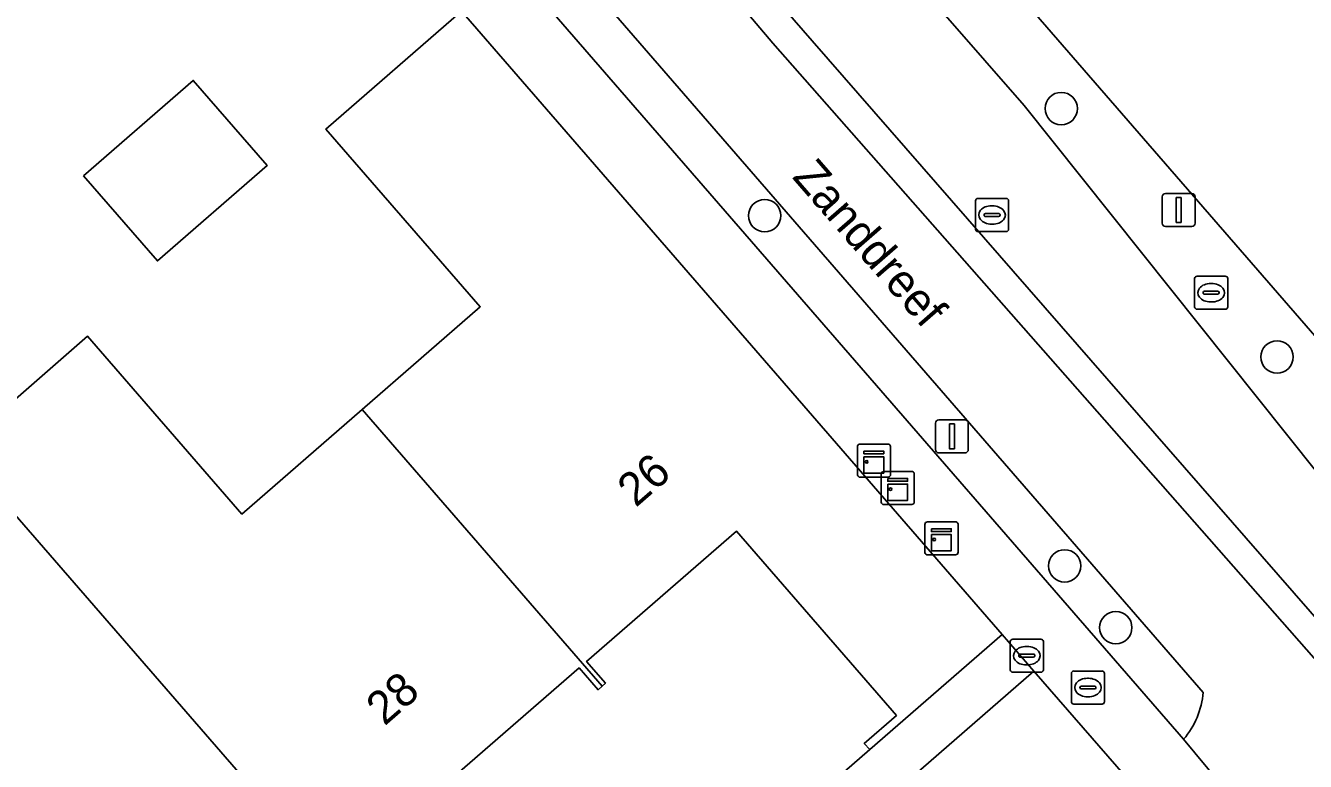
# Model space of a CAD drawing. Extents: x 155887 to 156869, y 383880 to 384678.
# Drawn here: x 156257.89 to 156296.57, y 384282.42 to 384304.63 of the extents above; entities that cross this region are included whole.
import ezdxf

# ---------------------------------------------------------------- set-up
doc = ezdxf.new("R2010")
doc.units = 0
for name, color, linetype in [('IMGEO_Berm_groen', 7, 'Continuous'), ('IMGEO_Boom', 7, 'Continuous'), ('IMGEO_Brandkraan', 7, 'Continuous'), ('IMGEO_Erf', 7, 'Continuous'), ('IMGEO_Fietspad_gesloten', 7, 'Continuous'), ('IMGEO_Greppel_droge_sloot', 7, 'Continuous'), ('IMGEO_Kast', 7, 'Continuous'), ('IMGEO_Kolk', 7, 'Continuous'), ('IMGEO_Lichtmast', 7, 'Continuous'), ('IMGEO_Openbare_ruimte_label', 7, 'Continuous'), ('IMGEO_OVBaan_gesloten', 7, 'Continuous'), ('IMGEO_Pand', 7, 'Continuous'), ('IMGEO_Pand_nummerreeks', 7, 'Continuous'), ('IMGEO_Parkeervlak_open', 7, 'Continuous'), ('IMGEO_Rioolput', 7, 'Continuous'), ('IMGEO_Voetpad_open', 7, 'Continuous')]:
    doc.layers.add(name, color=color, linetype=linetype)

msp = doc.modelspace()

# ---------------------------------------------------------------- linework, layer by layer
at = {"layer": 'IMGEO_Berm_groen'}
for points in [[(156336.14, 384250), (156299.846, 384291.826), (156254.404, 384344.112), (156249.976, 384340.147), (156249.797, 384339.996), (156255.055, 384333.785), (156258.691, 384329.477), (156261.912, 384325.993), (156263.306, 384324.351), (156280.478, 384304.105), (156290.275, 384292.985), (156298.297, 384283.879), (156305.293, 384275.816), (156311.875, 384268.489), (156315.179, 384264.541), (156318.171, 384261.203), (156320.09, 384258.879)], [(156248.065, 384336.788), (156247.015, 384335.884), (156292.888, 384283.087)], [(156293.476, 384284.503), (156248.065, 384336.788)]]:
    msp.add_lwpolyline(points, dxfattribs=at)
msp.add_lwpolyline([(156368.15, 384206.984), (156366.826, 384207.656), (156347.42, 384229.84), (156346.712, 384229.424), (156328.888, 384250), (156300.438, 384282.682), (156281.665, 384304.177), (156250.888, 384339.475), (156253.839, 384342.093), (156284.501, 384306.304), (156288.071, 384302.223), (156298.666, 384288.958), (156332.451, 384250), (156348.753, 384231.201), (156348.499, 384230.919), (156368.479, 384208.305), (156368.644, 384207.432)], close=True, dxfattribs=at)
msp.add_arc((156290.997, 384284.703), 2.487, 319.4991, 355.3992, dxfattribs=at)
at = {"layer": 'IMGEO_Boom'}
for centre in [(156289.189, 384302.13), (156280.228, 384298.897), (156295.711, 384294.631), (156289.292, 384288.323), (156290.837, 384286.459)]:
    msp.add_circle(centre, 0.489, dxfattribs=at)
at = {"layer": 'IMGEO_Brandkraan'}
for p, q in [((156287.723, 384286.111), (156288.575, 384286.111)), ((156287.648, 384285.185), (156287.648, 384286.037)), ((156288.136, 384285.891), (156288.161, 384285.891)), ((156288.649, 384286.037), (156288.649, 384285.185)), ((156287.907, 384285.605), (156287.907, 384285.617)), ((156288.345, 384285.568), (156287.947, 384285.568)), ((156287.95, 384285.654), (156288.348, 384285.654)), ((156288.391, 384285.617), (156288.391, 384285.605)), ((156288.575, 384285.111), (156287.723, 384285.111)), ((156288.159, 384285.331), (156288.134, 384285.331)), ((156289.495, 384284.223), (156289.495, 384285.075)), ((156289.57, 384285.149), (156290.422, 384285.149)), ((156290.496, 384285.075), (156290.496, 384284.223)), ((156289.754, 384284.643), (156289.754, 384284.655)), ((156290.192, 384284.606), (156289.794, 384284.606)), ((156289.797, 384284.692), (156290.195, 384284.692)), ((156289.983, 384284.929), (156290.008, 384284.929)), ((156290.238, 384284.655), (156290.238, 384284.643)), ((156290.006, 384284.369), (156289.981, 384284.369)), ((156290.422, 384284.149), (156289.57, 384284.149))]:
    msp.add_line(p, q, dxfattribs=at)
for points in [[(156287.723, 384286.111), (156288.575, 384286.111)], [(156287.648, 384285.185), (156287.648, 384286.037)], [(156288.649, 384286.037), (156288.649, 384285.185)], [(156288.575, 384285.111), (156287.723, 384285.111)], [(156289.495, 384284.223), (156289.495, 384285.075)], [(156289.57, 384285.149), (156290.422, 384285.149)], [(156290.496, 384285.075), (156290.496, 384284.223)], [(156290.422, 384284.149), (156289.57, 384284.149)]]:
    msp.add_lwpolyline(points, dxfattribs=at)
for centre, radius, start, end in [((156287.725, 384286.035), 0.0765, 91.552, 178.448), ((156287.725, 384286.035), 0.0765, 91.552, 178.448), ((156288.573, 384286.035), 0.0765, 1.552, 88.448), ((156288.573, 384286.035), 0.0765, 1.552, 88.448), ((156287.947, 384285.614), 0.0403, 85.8775, 175.7526), ((156287.944, 384285.604), 0.0366, 178.938, 274.7102), ((156288.348, 384285.611), 0.043, 264.8664, 352.4533), ((156288.352, 384285.616), 0.0386, 1.7309, 96.639), ((156287.725, 384285.187), 0.0765, 181.552, 268.448), ((156287.725, 384285.187), 0.0765, 181.552, 268.448), ((156288.573, 384285.187), 0.0765, 271.552, 358.448), ((156288.573, 384285.187), 0.0765, 271.552, 358.448), ((156289.572, 384285.073), 0.0765, 91.552, 178.448), ((156289.572, 384285.073), 0.0765, 91.552, 178.448), ((156290.42, 384285.073), 0.0765, 1.552, 88.448), ((156290.42, 384285.073), 0.0765, 1.552, 88.448), ((156289.794, 384284.652), 0.0403, 85.8775, 175.7526), ((156289.791, 384284.642), 0.0366, 178.938, 274.7102), ((156290.195, 384284.649), 0.043, 264.8664, 352.4533), ((156290.199, 384284.654), 0.0386, 1.7309, 96.639), ((156289.572, 384284.225), 0.0765, 181.552, 268.448), ((156289.572, 384284.225), 0.0765, 181.552, 268.448), ((156290.42, 384284.225), 0.0765, 271.552, 358.448), ((156290.42, 384284.225), 0.0765, 271.552, 358.448)]:
    msp.add_arc(centre, radius, start, end, dxfattribs=at)
for centre, major_axis, ratio, start_param, end_param in [((156288.135, 384285.611), (-0.387, 0.002), 0.722429, 4.712389, 7.853982), ((156288.16, 384285.611), (-0.39, 0.002), 0.717154, 1.570796, 4.712389), ((156289.982, 384284.649), (-0.387, 0.002), 0.722429, 4.712389, 7.853982), ((156290.007, 384284.649), (-0.39, 0.002), 0.717154, 1.570796, 4.712389)]:
    msp.add_ellipse(centre, major_axis=major_axis, ratio=ratio, start_param=start_param, end_param=end_param, dxfattribs=at)
at = {"layer": 'IMGEO_Erf'}
msp.add_lwpolyline([(156222.851, 384268.495), (156226.866, 384272.016), (156227.303, 384271.525), (156229.535, 384269.017), (156234.215, 384263.633), (156237.846, 384266.788), (156241.446, 384269.916), (156236.782, 384275.282), (156240.753, 384278.732), (156244.648, 384282.117), (156249.312, 384276.751), (156252.943, 384279.906), (156256.551, 384283.041), (156251.887, 384288.407), (156254.725, 384290.873), (156252.708, 384293.195), (156255.163, 384295.328), (156257.18, 384293.007), (156259.767, 384295.255), (156264.431, 384289.889), (156268.062, 384293.044), (156271.633, 384296.146), (156266.969, 384301.512), (156271.067, 384305.073)], dxfattribs=at)
for points in [[(156259.643, 384300.098), (156262.957, 384302.978), (156265.188, 384300.411), (156261.874, 384297.531)], [(156283.4, 384282.776), (156283.237, 384282.965), (156284.208, 384283.81), (156279.374, 384289.373), (156274.845, 384285.438), (156275.416, 384284.782), (156275.317, 384284.696), (156275.19, 384284.585), (156274.619, 384285.241), (156270.089, 384281.305), (156274.923, 384275.741), (156275.868, 384276.562), (156276.031, 384276.373)]]:
    msp.add_lwpolyline(points, close=True, dxfattribs=at)
at = {"layer": 'IMGEO_Fietspad_gesloten'}
for points in [[(156249.797, 384339.996), (156248.552, 384341.467), (156247.246, 384342.959), (156244.762, 384340.663), (156246.616, 384338.427), (156248.065, 384336.788), (156293.476, 384284.503)], [(156320.09, 384258.879), (156318.171, 384261.203), (156315.179, 384264.541), (156311.875, 384268.489), (156305.293, 384275.816), (156298.297, 384283.879), (156290.275, 384292.985), (156280.478, 384304.105), (156263.306, 384324.351), (156261.912, 384325.993), (156258.691, 384329.477), (156255.055, 384333.785), (156249.797, 384339.996)], [(156292.888, 384283.087), (156295.435, 384280.018)]]:
    msp.add_lwpolyline(points, dxfattribs=at)
msp.add_arc((156290.997, 384284.703), 2.487, 319.4991, 355.3992, dxfattribs=at)
at = {"layer": 'IMGEO_Greppel_droge_sloot'}
msp.add_lwpolyline([(156368.15, 384206.984), (156368.644, 384207.432), (156368.479, 384208.305), (156348.499, 384230.919), (156348.753, 384231.201), (156332.451, 384250), (156298.666, 384288.958), (156288.071, 384302.223), (156284.501, 384306.304), (156253.839, 384342.093), (156250.888, 384339.475), (156281.665, 384304.177), (156300.438, 384282.682), (156328.888, 384250), (156346.712, 384229.424), (156347.42, 384229.84), (156366.826, 384207.656)], close=True, dxfattribs=at)
at = {"layer": 'IMGEO_Kast'}
for p, q in [((156283.031, 384291.076), (156283.031, 384291.917)), ((156283.031, 384291.917), (156283.031, 384291.076)), ((156283.106, 384292.001), (156283.947, 384292.001)), ((156283.947, 384292.001), (156283.106, 384292.001)), ((156284.031, 384291.926), (156284.031, 384291.085)), ((156284.031, 384291.085), (156284.031, 384291.926)), ((156283.824, 384291.175), (156284.665, 384291.175)), ((156284.665, 384291.175), (156283.824, 384291.175)), ((156283.956, 384291.001), (156283.115, 384291.001)), ((156283.115, 384291.001), (156283.956, 384291.001)), ((156283.749, 384290.25), (156283.749, 384291.091)), ((156283.749, 384291.091), (156283.749, 384290.25)), ((156284.749, 384291.1), (156284.749, 384290.259)), ((156284.749, 384290.259), (156284.749, 384291.1)), ((156284.674, 384290.175), (156283.833, 384290.175)), ((156283.833, 384290.175), (156284.674, 384290.175)), ((156285.145, 384289.654), (156285.986, 384289.654)), ((156285.986, 384289.654), (156285.145, 384289.654)), ((156285.07, 384288.729), (156285.07, 384289.57)), ((156285.07, 384289.57), (156285.07, 384288.729)), ((156286.07, 384289.579), (156286.07, 384288.738)), ((156286.07, 384288.738), (156286.07, 384289.579)), ((156285.995, 384288.654), (156285.154, 384288.654)), ((156285.154, 384288.654), (156285.995, 384288.654))]:
    msp.add_line(p, q, dxfattribs=at)
for points in [[(156283.226, 384291.791), (156283.826, 384291.791), (156283.826, 384291.706), (156283.226, 384291.706), (156283.226, 384291.791)], [(156283.226, 384291.616), (156283.826, 384291.616), (156283.826, 384291.127), (156283.226, 384291.127), (156283.226, 384291.616)], [(156283.944, 384290.965), (156284.544, 384290.965), (156284.544, 384290.88), (156283.944, 384290.88), (156283.944, 384290.965)], [(156283.944, 384290.79), (156284.544, 384290.79), (156284.544, 384290.301), (156283.944, 384290.301), (156283.944, 384290.79)], [(156285.265, 384289.444), (156285.865, 384289.444), (156285.865, 384289.359), (156285.265, 384289.359), (156285.265, 384289.444)], [(156285.265, 384289.269), (156285.865, 384289.269), (156285.865, 384288.78), (156285.265, 384288.78), (156285.265, 384289.269)]]:
    msp.add_lwpolyline(points, dxfattribs=at)
for centre in [(156283.31, 384291.465), (156284.028, 384290.639), (156285.349, 384289.118)]:
    msp.add_circle(centre, 0.0377, dxfattribs=at)
for centre, start, end in [((156283.109, 384291.923), 92.4484, 184.2845), ((156283.109, 384291.923), 92.4484, 184.2845), ((156283.953, 384291.923), 2.4484, 94.2845), ((156283.953, 384291.923), 2.4484, 94.2845), ((156283.827, 384291.097), 92.4484, 184.2845), ((156283.827, 384291.097), 92.4484, 184.2845), ((156284.671, 384291.097), 2.4484, 94.2845), ((156284.671, 384291.097), 2.4484, 94.2845), ((156283.109, 384291.079), 182.4484, 274.2845), ((156283.109, 384291.079), 182.4484, 274.2845), ((156283.953, 384291.079), 272.4484, 4.2845), ((156283.953, 384291.079), 272.4484, 4.2845), ((156283.827, 384290.253), 182.4484, 274.2845), ((156283.827, 384290.253), 182.4484, 274.2845), ((156284.671, 384290.253), 272.4484, 4.2845), ((156284.671, 384290.253), 272.4484, 4.2845), ((156285.148, 384289.576), 92.4484, 184.2845), ((156285.148, 384289.576), 92.4484, 184.2845), ((156285.992, 384289.576), 2.4484, 94.2845), ((156285.992, 384289.576), 2.4484, 94.2845), ((156285.148, 384288.732), 182.4484, 274.2845), ((156285.148, 384288.732), 182.4484, 274.2845), ((156285.992, 384288.732), 272.4484, 4.2845), ((156285.992, 384288.732), 272.4484, 4.2845)]:
    msp.add_arc(centre, 0.0779, start, end, dxfattribs=at)
at = {"layer": 'IMGEO_Kolk'}
for p, q in [((156286.598, 384298.491), (156286.598, 384299.343)), ((156286.673, 384299.417), (156287.525, 384299.417)), ((156287.599, 384299.343), (156287.599, 384298.491)), ((156286.857, 384298.911), (156286.857, 384298.923)), ((156287.295, 384298.874), (156286.897, 384298.874)), ((156286.9, 384298.96), (156287.298, 384298.96)), ((156287.086, 384299.197), (156287.111, 384299.197)), ((156287.341, 384298.923), (156287.341, 384298.911)), ((156287.109, 384298.637), (156287.084, 384298.637)), ((156287.525, 384298.417), (156286.673, 384298.417))]:
    msp.add_line(p, q, dxfattribs=at)
for points in [[(156286.598, 384298.491), (156286.598, 384299.343)], [(156286.673, 384299.417), (156287.525, 384299.417)], [(156287.599, 384299.343), (156287.599, 384298.491)], [(156287.525, 384298.417), (156286.673, 384298.417)]]:
    msp.add_lwpolyline(points, dxfattribs=at)
for centre, radius, start, end in [((156286.675, 384299.341), 0.0765, 91.552, 178.448), ((156286.675, 384299.341), 0.0765, 91.552, 178.448), ((156287.523, 384299.341), 0.0765, 1.552, 88.448), ((156287.523, 384299.341), 0.0765, 1.552, 88.448), ((156286.897, 384298.92), 0.0403, 85.8775, 175.7526), ((156286.894, 384298.91), 0.0366, 178.938, 274.7102), ((156287.298, 384298.917), 0.043, 264.8664, 352.4533), ((156287.302, 384298.922), 0.0386, 1.7309, 96.639), ((156286.675, 384298.493), 0.0765, 181.552, 268.448), ((156286.675, 384298.493), 0.0765, 181.552, 268.448), ((156287.523, 384298.493), 0.0765, 271.552, 358.448), ((156287.523, 384298.493), 0.0765, 271.552, 358.448)]:
    msp.add_arc(centre, radius, start, end, dxfattribs=at)
for centre, major_axis, ratio, start_param, end_param in [((156287.085, 384298.917), (-0.387, 0.002), 0.722429, 4.712389, 7.853982), ((156287.11, 384298.917), (-0.39, 0.002), 0.717154, 1.570796, 4.712389)]:
    msp.add_ellipse(centre, major_axis=major_axis, ratio=ratio, start_param=start_param, end_param=end_param, dxfattribs=at)
at = {"layer": 'IMGEO_Lichtmast'}
for p, q in [((156292.242, 384298.667), (156292.242, 384299.467)), ((156292.242, 384299.467), (156292.242, 384298.667)), ((156292.342, 384299.567), (156293.132, 384299.567)), ((156293.132, 384299.567), (156292.342, 384299.567)), ((156293.232, 384299.467), (156293.232, 384298.667)), ((156293.232, 384298.667), (156293.232, 384299.467)), ((156293.132, 384298.567), (156292.342, 384298.567)), ((156292.342, 384298.567), (156293.132, 384298.567)), ((156285.49, 384292.733), (156286.28, 384292.733)), ((156286.28, 384292.733), (156285.49, 384292.733)), ((156285.39, 384291.833), (156285.39, 384292.633)), ((156285.39, 384292.633), (156285.39, 384291.833)), ((156286.38, 384292.633), (156286.38, 384291.833)), ((156286.38, 384291.833), (156286.38, 384292.633)), ((156286.28, 384291.733), (156285.49, 384291.733)), ((156285.49, 384291.733), (156286.28, 384291.733))]:
    msp.add_line(p, q, dxfattribs=at)
for points in [[(156292.662, 384299.442), (156292.812, 384299.442), (156292.812, 384298.692), (156292.662, 384298.692), (156292.662, 384299.442)], [(156285.81, 384292.608), (156285.96, 384292.608), (156285.96, 384291.858), (156285.81, 384291.858), (156285.81, 384292.608)]]:
    msp.add_lwpolyline(points, dxfattribs=at)
for centre, start, end in [((156292.342, 384299.467), 90, 180), ((156292.342, 384299.467), 90, 180), ((156293.132, 384299.467), 0, 90), ((156293.132, 384299.467), 360, 90), ((156292.342, 384298.667), 180, 270), ((156292.342, 384298.667), 180, 270), ((156293.132, 384298.667), 270, 0), ((156293.132, 384298.667), 270, 0), ((156285.49, 384292.633), 90, 180), ((156285.49, 384292.633), 90, 180), ((156286.28, 384292.633), 0, 90), ((156286.28, 384292.633), 360, 90), ((156285.49, 384291.833), 180, 270), ((156285.49, 384291.833), 180, 270), ((156286.28, 384291.833), 270, 0), ((156286.28, 384291.833), 270, 0)]:
    msp.add_arc(centre, 0.1, start, end, dxfattribs=at)
at = {"layer": 'IMGEO_OVBaan_gesloten'}
msp.add_lwpolyline([(156344.918, 384250), (156310.449, 384289.788), (156259.398, 384348.45), (156254.404, 384344.112), (156299.846, 384291.826), (156336.14, 384250)], dxfattribs=at)
at = {"layer": 'IMGEO_Pand'}
for points in [[(156275.317, 384284.696), (156275.416, 384284.782), (156274.845, 384285.438), (156279.374, 384289.373), (156284.208, 384283.81), (156283.237, 384282.965), (156283.4, 384282.776), (156287.4, 384286.252), (156271.067, 384305.073), (156266.969, 384301.512), (156271.633, 384296.146), (156268.062, 384293.044)], [(156259.643, 384300.098), (156261.874, 384297.531), (156265.188, 384300.411), (156262.957, 384302.978)], [(156268.062, 384293.044), (156264.431, 384289.889), (156259.767, 384295.255), (156257.18, 384293.007), (156255.842, 384291.844), (156272.197, 384273.042), (156276.031, 384276.373), (156275.868, 384276.562), (156274.923, 384275.741), (156270.089, 384281.305), (156274.619, 384285.241), (156275.19, 384284.585), (156275.317, 384284.696)], [(156255.842, 384291.844), (156254.725, 384290.873), (156251.887, 384288.407), (156256.551, 384283.041), (156252.943, 384279.906), (156260.214, 384271.572), (156260.319, 384271.664), (156259.748, 384272.32), (156264.277, 384276.255), (156269.111, 384270.691), (156268.169, 384269.873), (156268.332, 384269.684), (156272.197, 384273.042)]]:
    msp.add_lwpolyline(points, close=True, dxfattribs=at)
at = {"layer": 'IMGEO_Parkeervlak_open'}
msp.add_lwpolyline([(156291.002, 384281.43), (156291.342, 384281.726), (156288.362, 384285.147), (156247.93, 384250), (156242.787, 384245.529), (156245.758, 384242.109), (156254.838, 384250)], close=True, dxfattribs=at)
at = {"layer": 'IMGEO_Rioolput'}
for p, q in [((156293.219, 384296.144), (156293.219, 384296.996)), ((156293.294, 384297.07), (156294.146, 384297.07)), ((156294.22, 384296.996), (156294.22, 384296.144)), ((156293.478, 384296.564), (156293.478, 384296.576)), ((156293.521, 384296.613), (156293.919, 384296.613)), ((156293.707, 384296.85), (156293.732, 384296.85)), ((156293.962, 384296.576), (156293.962, 384296.564)), ((156293.916, 384296.527), (156293.518, 384296.527)), ((156293.73, 384296.29), (156293.705, 384296.29)), ((156294.146, 384296.07), (156293.294, 384296.07))]:
    msp.add_line(p, q, dxfattribs=at)
for points in [[(156293.219, 384296.144), (156293.219, 384296.996)], [(156293.294, 384297.07), (156294.146, 384297.07)], [(156294.22, 384296.996), (156294.22, 384296.144)], [(156294.146, 384296.07), (156293.294, 384296.07)]]:
    msp.add_lwpolyline(points, dxfattribs=at)
for centre, radius, start, end in [((156293.296, 384296.994), 0.0765, 91.552, 178.448), ((156293.296, 384296.994), 0.0765, 91.552, 178.448), ((156294.144, 384296.994), 0.0765, 1.552, 88.448), ((156294.144, 384296.994), 0.0765, 1.552, 88.448), ((156293.518, 384296.573), 0.0403, 85.8775, 175.7526), ((156293.515, 384296.563), 0.0366, 178.938, 274.7102), ((156293.919, 384296.57), 0.043, 264.8664, 352.4533), ((156293.923, 384296.575), 0.0386, 1.7309, 96.639), ((156293.296, 384296.146), 0.0765, 181.552, 268.448), ((156293.296, 384296.146), 0.0765, 181.552, 268.448), ((156294.144, 384296.146), 0.0765, 271.552, 358.448), ((156294.144, 384296.146), 0.0765, 271.552, 358.448)]:
    msp.add_arc(centre, radius, start, end, dxfattribs=at)
for centre, major_axis, ratio, start_param, end_param in [((156293.706, 384296.57), (-0.387, 0.002), 0.722429, 4.712389, 7.853982), ((156293.731, 384296.57), (-0.39, 0.002), 0.717154, 1.570796, 4.712389)]:
    msp.add_ellipse(centre, major_axis=major_axis, ratio=ratio, start_param=start_param, end_param=end_param, dxfattribs=at)
at = {"layer": 'IMGEO_Voetpad_open'}
msp.add_lwpolyline([(156295.435, 384280.018), (156292.888, 384283.087), (156247.015, 384335.884), (156245.448, 384334.593), (156249.355, 384330.069), (156256.341, 384321.946), (156258.613, 384319.304), (156271.067, 384305.073), (156287.4, 384286.252), (156288.362, 384285.147), (156291.342, 384281.726), (156296.121, 384276.22), (156318.88, 384250), (156326.424, 384241.306)], dxfattribs=at)
msp.add_lwpolyline([(156288.362, 384285.147), (156287.4, 384286.252), (156283.4, 384282.776), (156276.031, 384276.373), (156272.197, 384273.042), (156268.332, 384269.684), (156260.934, 384263.255), (156257.1, 384259.924), (156253.235, 384256.566), (156245.845, 384250.143), (156245.68, 384250), (156241.836, 384246.66), (156242.787, 384245.529), (156247.93, 384250)], close=True, dxfattribs=at)

# ---------------------------------------------------------------- texts
at = {"layer": 'IMGEO_Openbare_ruimte_label'}
msp.add_text('Zanddreef', height=1, rotation=310.9865, dxfattribs=at).set_placement((156281.035, 384300.051))
at = {"layer": 'IMGEO_Pand_nummerreeks'}
for s, rotation, p in [('26', 40.9888, (156276.331, 384290.068)), ('28', 40.9894, (156268.738, 384283.471))]:
    msp.add_text(s, height=1, rotation=rotation, dxfattribs=at).set_placement(p)

doc.saveas('drawing.dxf')
